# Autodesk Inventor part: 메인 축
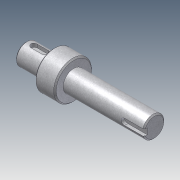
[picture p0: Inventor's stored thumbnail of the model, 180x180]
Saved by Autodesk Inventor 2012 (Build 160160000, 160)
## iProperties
Company: 한국ATC센터
Created: 2014-10
Part Number: 메인 축
Document SubType Name: Modeling
Designer: KYOUNG IL JANG
Density: 1 g/cm^3
Mass: 29.2926 g
Surface Area: 74.3518 cm^2
Volume: 29.2926 cm^3
Material: 기본값
Author: KYOUNG IL JANG
Revision Number: 1
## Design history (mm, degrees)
sketch "스케치1"
  geometry: L1 (10.497, -57.5)-(112.497, -57.5); L2 (10.497, -66)-(32.497, -66); L3 (32.497, -72.5)-(46.5, -72.5); L4 (46.5, -66)-(112.497, -66); L5 (112.497, -66)-(112.497, -57.5); L6 (10.497, -66)-(10.497, -57.5); L7 (46.5, -69.749)-(46.5, -45.251) reference; L8 (46.5, -72.5)-(46.5, -66); L9 (32.497, -72.5)-(32.497, -66); L10 (32.497, -35)-(32.497, -80) reference; 3 further points
  constraints: 16 end point, 3 point on line, 2 parallel, 2 perpendicular, 1 collinear, 1 horizontal, 1 midpoint
  dimensions: "d0" = 17 diameter of L4 L1; "d1" = 30 diameter of L3 L1; "d2" = 22 distance of L2.start L2.end; "d3" = 65.99692 distance of L4.start L4.end (derived); "d5" = 17 diameter of L2 L1; "d19" = 80 distance between parallel lines of L5 L9
revolve "회전1" sketch "스케치1" stored, may be unused: angle "d4" = 90 deg
chamfer "모따기1" distance "d6" = 1; stored, may be unused: second distance "d7" = 2, angle "d8" = 45 deg
node "작업 평면1"
sketch "스케치2"
  geometry: L1 (-11, -7.5)-(-11, 7.5) reference; L2 (-4.5, 2.5)-(4.5, 2.5); L3 (4.5, -2.5)-(-4.5, -2.5); A1 r 2.5 centre (4.5, 0) between (4.5, -2.5) and (4.5, 2.5); A2 r 2.5 centre (-4.5, 0) between (-4.5, 2.5) and (-4.5, -2.5); 2 further points
  constraints: 4 end point, 4 point on circle, 4 tangent, 2 centre point, 1 horizontal alignment, 1 midpoint, 1 parallel, 1 perpendicular
  dimensions: "d9" = 5 distance between parallel lines of L3 L2; "d10" = 14 dimension on A1 A2; "d11" = 4 distance edge to line of A2 L1
extrude "돌출1" cut sketch "스케치2" distance "d12" = 3; taper "d13" = 0 deg
node "작업 평면2"
sketch "스케치3"
  geometry: L1 (32.998, 7.5)-(32.998, -7.5) reference; L2 (32.998, 2.5)-(17.498, 2.5); L3 (17.498, -2.5)-(32.998, -2.5); A1 r 2.5 centre (17.498, 0) between (17.498, 2.5) and (17.498, -2.5); 2 further points
  constraints: 4 end point, 2 perpendicular, 2 point on circle, 2 point on line, 2 tangent, 1 centre point, 1 horizontal alignment, 1 midpoint
  dimensions: "d14" = 5 distance between parallel lines of L3 L2; "d15" = 18 dimension on A1 L1
extrude "돌출2" cut sketch "스케치3" distance "d16" = 3; taper "d17" = 0 deg
node "솔리드1"
node "참조4"
node "참조5"
